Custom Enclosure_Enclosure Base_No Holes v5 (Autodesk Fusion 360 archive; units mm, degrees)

design "Custom Enclosure_Enclosure Base_No Holes" references "autodesk 3ax table head yxz"
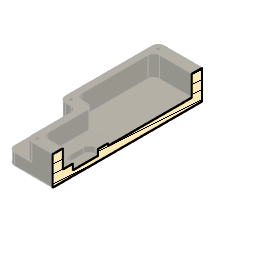
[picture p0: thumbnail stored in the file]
base_feature "Base Feature"
sketch "Sketch1" plane through (0, 0, 0) normal (0, 1, 0) x axis (1, 0, 0)
  line L1 (0, 34.798) -> (-27.94, 34.798)
  line L2 (0, 0) -> (0, 34.798)
  line L3 (-27.94, 0) -> (0, 0)
  line L4 (-27.94, 34.798) -> (-27.94, 0)
  line L5 (15, 44.5773) -> (15, 106.9773)
  line L6 (-43, 44.5773) -> (15, 44.5773)
  line L7 (-43, 106.9773) -> (-43, 44.5773)
  line L8 (15, 106.9773) -> (-43, 106.9773)
  line L9 (13.2, 46.3773) -> (11.7, 46.3773)
  line L10 (13.2, 105.1773) -> (13.2, 46.3773)
  line L11 (11.7, 105.1773) -> (13.2, 105.1773)
  line L12 (11.7, 46.3773) -> (11.7, 105.1773)
  line L13 (10, 44.5773) -> (10, 44.798)
  line L14 (-37.94, 44.798) -> (-37.94, 44.5773)
  line L15 (25, 37.5773) -> (25, 113.9773)
  line L16 (-53, 113.9773) -> (-53, 37.5773)
  line L17 (20, 118.9773) -> (-48, 118.9773)
  line L18 (-32.94, -12) -> (5, -12)
  line L19 (-37.94, 27.5773) -> (-37.94, -7)
  line L20 (-37.94, 44.798) -> (-37.94, 44.5773)
  line L21 (15, 32.5773) -> (20, 32.5773)
  line L22 (-48, 32.5773) -> (-42.94, 32.5773)
  line L23 (10, 44.5773) -> (10, 44.798)
  line L24 (10, -7) -> (10, 27.5773)
  circle C1 centre (-24.13, 1.524) radius 0.5
  circle C2 centre (-24.13, 5.09) radius 0.5
  circle C3 centre (-24.13, 7.63) radius 0.5
  circle C4 centre (-24.13, 10.17) radius 0.5
  circle C5 centre (-24.13, 12.71) radius 0.5
  circle C6 centre (-18.542, 2.54) radius 1.1
  circle C7 centre (-15.322, 17.286) radius 0.15
  circle C8 centre (-14.772, 16.736) radius 0.15
  circle C9 centre (-14.222, 17.286) radius 0.15
  circle C10 centre (-13.672, 16.736) radius 0.15
  circle C11 centre (-13.122, 17.286) radius 0.15
  circle C12 centre (-24.13, 18.288) radius 0.5
  circle C13 centre (-24.13, 20.828) radius 0.5
  circle C14 centre (-24.13, 23.368) radius 0.5
  circle C15 centre (-24.13, 25.908) radius 0.5
  circle C16 centre (-24.13, 28.448) radius 0.5
  circle C17 centre (-24.13, 30.988) radius 0.5
  circle C18 centre (-15.322, 18.386) radius 0.15
  circle C19 centre (-14.772, 17.836) radius 0.15
  circle C20 centre (-14.222, 18.386) radius 0.15
  circle C21 centre (-14.772, 18.936) radius 0.15
  circle C22 centre (-13.672, 17.836) radius 0.15
  circle C23 centre (-13.672, 18.936) radius 0.15
  circle C24 centre (-13.122, 18.386) radius 0.15
  circle C25 centre (-1.778, 1.778) radius 1.1
  circle C26 centre (-1.778, 33.02) radius 1.1
  circle C27 centre (-14, 97.9773) radius 1.44
  circle C28 centre (-14, 53.5773) radius 1.44
  arc A1 centre (-42.94, 27.5773) radius 5 clockwise from (-42.94, 32.5773) to (-37.94, 27.5773)
  arc A2 centre (-48, 37.5773) radius 5 clockwise from (-48, 32.5773) to (-53, 37.5773)
  arc A3 centre (15, 27.5773) radius 5 clockwise from (10, 27.5773) to (15, 32.5773)
  arc A4 centre (20, 37.5773) radius 5 clockwise from (25, 37.5773) to (20, 32.5773)
  arc A5 centre (-32.94, -7) radius 5 clockwise from (-32.94, -12) to (-37.94, -7)
  arc A6 centre (5, -7) radius 5 clockwise from (10, -7) to (5, -12)
  arc A7 centre (-48, 113.9773) radius 5 clockwise from (-53, 113.9773) to (-48, 118.9773)
  arc A8 centre (20, 113.9773) radius 5 clockwise from (20, 118.9773) to (25, 113.9773)
  point P44 (-37.94, 44.5773)
  point P45 (10, 44.5773)
  parallel L2 L13
  coincident L6 P44
  coincident L6 P45
  parallel L2 L23
  parallel L3 L18
  parallel L4 L19
  collinear L19 L20
  parallel L5 L15
  parallel L6 L21
  parallel L7 L16
  parallel L8 L17
  collinear L21 L22
  collinear L23 L24
  tangent L19 A1
  tangent L22 A1
  tangent L16 A2
  tangent L22 A2
  equal A1 A2
  tangent L21 A3
  tangent L24 A3
  equal A1 A3
  tangent L15 A4
  tangent L21 A4
  equal A1 A4
  tangent L18 A5
  tangent L19 A5
  equal A1 A5
  tangent L18 A6
  tangent L24 A6
  equal A1 A6
  tangent L16 A7
  tangent L17 A7
  equal A1 A7
  tangent L15 A8
  tangent L17 A8
  equal A1 A8
  dimension "d20" radius A1 = 5
  dimension "d33" distance L8 L17 = 12
  dimension "d34" distance L6 L22 = 12
  dimension "d35" distance L3 L18 = 12
extrude "Extrude1" new body sketch "Sketch1" profile of L15 L22 L16 L17 L24 L20 L18 A1 A2 A3 A4 A5 A6 A7 A8 along normal blind 18 and against normal blind 7.4
sketch "Sketch2" plane through (0, 0, 0) normal (0, 1, 0) x axis (1, 0, 0)
  line L1 (0, 34.798) -> (-27.94, 34.798)
  line L2 (0, 0) -> (0, 34.798)
  line L3 (-27.94, 0) -> (0, 0)
  line L4 (-27.94, 34.798) -> (-27.94, 0)
  line L5 (15, 44.5773) -> (15, 106.9773)
  line L6 (-43, 44.5773) -> (15, 44.5773)
  line L7 (-43, 106.9773) -> (-43, 44.5773)
  line L8 (15, 106.9773) -> (-43, 106.9773)
  line L9 (13.2, 46.3773) -> (11.7, 46.3773)
  line L10 (13.2, 105.1773) -> (13.2, 46.3773)
  line L11 (11.7, 105.1773) -> (13.2, 105.1773)
  line L12 (11.7, 46.3773) -> (11.7, 105.1773)
  line L13 (20, 46.5773) -> (20, 104.9773)
  line L14 (-48, 104.9773) -> (-48, 46.5773)
  line L15 (15, 109.9773) -> (-43, 109.9773)
  line L16 (-27.94, -3) -> (0, -3)
  line L17 (-32.94, 36.5773) -> (-32.94, 2)
  line L18 (5, 2) -> (5, 36.5773)
  line L19 (10, 41.5773) -> (15, 41.5773)
  line L20 (-43, 41.5773) -> (-37.94, 41.5773)
  circle C1 centre (-24.13, 1.524) radius 0.5
  circle C2 centre (-24.13, 5.09) radius 0.5
  circle C3 centre (-24.13, 7.63) radius 0.5
  circle C4 centre (-24.13, 10.17) radius 0.5
  circle C5 centre (-24.13, 12.71) radius 0.5
  circle C6 centre (-18.542, 2.54) radius 1.1
  circle C7 centre (-15.322, 17.286) radius 0.15
  circle C8 centre (-14.772, 16.736) radius 0.15
  circle C9 centre (-14.222, 17.286) radius 0.15
  circle C10 centre (-13.672, 16.736) radius 0.15
  circle C11 centre (-13.122, 17.286) radius 0.15
  circle C12 centre (-24.13, 18.288) radius 0.5
  circle C13 centre (-24.13, 20.828) radius 0.5
  circle C14 centre (-24.13, 23.368) radius 0.5
  circle C15 centre (-24.13, 25.908) radius 0.5
  circle C16 centre (-24.13, 28.448) radius 0.5
  circle C17 centre (-24.13, 30.988) radius 0.5
  circle C18 centre (-15.322, 18.386) radius 0.15
  circle C19 centre (-14.772, 17.836) radius 0.15
  circle C20 centre (-14.222, 18.386) radius 0.15
  circle C21 centre (-14.772, 18.936) radius 0.15
  circle C22 centre (-13.672, 17.836) radius 0.15
  circle C23 centre (-13.672, 18.936) radius 0.15
  circle C24 centre (-13.122, 18.386) radius 0.15
  circle C25 centre (-1.778, 1.778) radius 1.1
  circle C26 centre (-1.778, 33.02) radius 1.1
  circle C27 centre (-14, 97.9773) radius 1.44
  circle C28 centre (-14, 53.5773) radius 1.44
  arc A1 centre (-43, 46.5773) radius 5 clockwise from (-43, 41.5773) to (-48, 46.5773)
  arc A2 centre (-37.94, 36.5773) radius 5 clockwise from (-37.94, 41.5773) to (-32.94, 36.5773)
  arc A3 centre (-27.94, 2) radius 5 clockwise from (-27.94, -3) to (-32.94, 2)
  arc A4 centre (0, 2) radius 5 clockwise from (5, 2) to (0, -3)
  arc A5 centre (10, 36.5773) radius 5 clockwise from (5, 36.5773) to (10, 41.5773)
  arc A6 centre (15, 46.5773) radius 5 clockwise from (20, 46.5773) to (15, 41.5773)
  arc A7 centre (-43, 104.9773) radius 5 clockwise from (-48, 104.9773) to (-43, 109.9773)
  arc A8 centre (15, 104.9773) radius 5 clockwise from (15, 109.9773) to (20, 104.9773)
  parallel L3 L16
  parallel L4 L17
  parallel L2 L18
  parallel L5 L13
  parallel L6 L19
  parallel L7 L14
  parallel L8 L15
  collinear L19 L20
  tangent L14 A1
  tangent L20 A1
  tangent L20 A2
  tangent L17 A2
  tangent L16 A3
  tangent L17 A3
  equal A2 A3
  tangent L16 A4
  tangent L18 A4
  equal A2 A4
  tangent L19 A5
  tangent L18 A5
  equal A2 A5
  tangent L13 A6
  tangent L19 A6
  equal A2 A6
  tangent L14 A7
  tangent L15 A7
  equal A2 A7
  tangent L13 A8
  tangent L15 A8
  equal A2 A8
  dimension "d23" radius A1 = 5
  dimension "d24" radius A2 = 5
  dimension "d30" distance L8 L15 = 3
  dimension "d31" distance L6 L20 = 3
  dimension "d32" distance L3 L16 = 3
extrude "Extrude4" cut sketch "Sketch2" profile of L14 L13 L20 L15 L16 L18 L17 A1 A2 A3 A4 A5 A6 A7 A8 to an object
sketch "Sketch9" plane through (0, 0, 0) normal (0, 1, 0) x axis (-1, 0, 0)
  line L1 (-20, -104.9773) -> (-20, -46.5773)
  line L2 (43, -109.9773) -> (-15, -109.9773)
  line L3 (48, -46.5773) -> (48, -104.9773)
  line L4 (37.94, -41.5773) -> (43, -41.5773)
  line L5 (32.94, -2) -> (32.94, -36.5773)
  line L6 (0, 3) -> (27.94, 3)
  line L7 (-5, -36.5773) -> (-5, -2)
  line L8 (-15, -41.5773) -> (-10, -41.5773)
  line L9 (-5, -36.5773) -> (32.94, -36.5773)
  arc A1 centre (-15, -46.5773) radius 5 clockwise from (-20, -46.5773) to (-15, -41.5773)
  arc A2 centre (-15, -104.9773) radius 5 clockwise from (-15, -109.9773) to (-20, -104.9773)
  arc A3 centre (43, -104.9773) radius 5 clockwise from (48, -104.9773) to (43, -109.9773)
  arc A4 centre (43, -46.5773) radius 5 clockwise from (43, -41.5773) to (48, -46.5773)
  arc A5 centre (37.94, -36.5773) radius 5 clockwise from (37.94, -41.5773) to (32.94, -36.5773)
  arc A6 centre (27.94, -2) radius 5 clockwise from (27.94, 3) to (32.94, -2)
  arc A7 centre (0, -2) radius 5 clockwise from (-5, -2) to (0, 3)
  arc A8 centre (-10, -36.5773) radius 5 clockwise from (-5, -36.5773) to (-10, -41.5773)
  point P15 (32.94, -36.5773)
  point P26 (32.94, -36.5773)
  point P23 (-5, -36.5773)
  point P27 (-5, -36.5773)
  coincident P15 P26
  coincident P23 P27
extrude "Extrude9" add sketch "Sketch9" profile of L5 A6 L6 A7 L7 L9 along normal blind 2
sketch "Sketch3" plane through (0, 2, 0) normal (0, 1, 0) x axis (-1, 0, 0)
  line L1 (0, 5) -> (27.94, 5)
  line L2 (-5, -106.9773) -> (-5, 0)
  line L3 (53, -111.9773) -> (0, -111.9773)
  line L4 (37.94, -39.5773) -> (53, -39.5773)
  line L5 (32.94, 0) -> (32.94, -34.5773)
  line L6 (19.713, -21.28) -> (19.713, -12.23)
  line L7 (9.713, -12.23) -> (9.713, -21.28)
  line L8 (9.713, -16.755) -> (19.713, -16.755)
  line L9 (17.213, -5.755) -> (12.213, -5.755)
  line L10 (22.213, -22.755) -> (22.213, -10.755)
  line L11 (12.213, -27.755) -> (17.213, -27.755)
  line L12 (7.213, -10.755) -> (7.213, -22.755)
  line L13 (22.213, -27.755) -> (7.213, -5.755)
  line L14 (7.213, -27.755) -> (22.213, -5.755)
  line L15 (53, -39.5773) -> (53, -111.9773)
  line L16 (-20, -104.9773) -> (-20, -46.5773)
  line L17 (43, -109.9773) -> (-15, -109.9773)
  line L18 (48, -46.5773) -> (48, -104.9773)
  line L19 (37.94, -41.5773) -> (43, -41.5773)
  line L20 (-15, -41.5773) -> (-10, -41.5773)
  line L21 (-5, -36.5773) -> (32.94, -36.5773)
  line L22 (0, 3) -> (27.94, 3)
  line L23 (-5, -36.5773) -> (-5, -2)
  line L24 (32.94, -36.5773) -> (-5, -36.5773)
  line L25 (32.94, -2) -> (32.94, -36.5773)
  arc A1 centre (27.94, 0) radius 5 clockwise from (27.94, 5) to (32.94, 0)
  arc A2 centre (0, 0) radius 5 clockwise from (-5, 0) to (0, 5)
  arc A3 centre (0, -106.9773) radius 5 clockwise from (0, -111.9773) to (-5, -106.9773)
  arc A4 centre (37.94, -34.5773) radius 5 clockwise from (37.94, -39.5773) to (32.94, -34.5773)
  arc A5 centre (17.213, -22.755) radius 5 clockwise from (22.213, -22.755) to (17.213, -27.755)
  arc A6 centre (17.213, -10.755) radius 5 clockwise from (17.213, -5.755) to (22.213, -10.755)
  arc A7 centre (12.213, -10.755) radius 5 clockwise from (7.213, -10.755) to (12.213, -5.755)
  arc A8 centre (12.213, -22.755) radius 5 clockwise from (12.213, -27.755) to (7.213, -22.755)
  arc A9 centre (-15, -46.5773) radius 5 clockwise from (-20, -46.5773) to (-15, -41.5773)
  arc A10 centre (-15, -104.9773) radius 5 clockwise from (-15, -109.9773) to (-20, -104.9773)
  arc A11 centre (43, -104.9773) radius 5 clockwise from (48, -104.9773) to (43, -109.9773)
  arc A12 centre (43, -46.5773) radius 5 clockwise from (43, -41.5773) to (48, -46.5773)
  arc A13 centre (37.94, -36.5773) radius 5 clockwise from (37.94, -41.5773) to (32.94, -36.5773)
  arc A14 centre (-10, -36.5773) radius 5 clockwise from (-5, -36.5773) to (-10, -41.5773)
  arc A15 centre (27.94, -2) radius 5 clockwise from (27.94, 3) to (32.94, -2)
  arc A16 centre (0, -2) radius 5 clockwise from (-5, -2) to (0, 3)
  point P20 (19.713, -16.755)
  point P21 (9.713, -16.755)
  point P26 (14.713, -16.755)
  point P24 (22.213, -27.755)
  point P23 (22.213, -5.755)
  point P22 (7.213, -5.755)
  point P25 (7.213, -27.755)
  midpoint L6 P20
  midpoint L7 P21
  horizontal L9
  perpendicular L9 L10
  parallel L9 L11
  parallel L10 L12
  coincident L13 P26
  coincident L14 P26
  midpoint L8 P26
  coincident P24 L11
  coincident P24 L10
  tangent L11 A5
  tangent L10 A5
  coincident P23 L10
  coincident P23 L9
  tangent L10 A6
  tangent L9 A6
  equal A5 A6
  coincident P22 L12
  coincident P22 L9
  tangent L12 A7
  tangent L9 A7
  equal A5 A7
  coincident P25 L11
  coincident P25 L12
  tangent L11 A8
  tangent L12 A8
  equal A5 A8
  dimension "d13" distance P22 P23 = 15
  dimension "d14" distance P22 P25 = 22
  dimension "d17" radius A5 = 5
extrude "Extrude3" cut sketch "Sketch3" profile of L9 L10 L11 L12 A5 A6 A7 A8 against normal blind 5
sketch "Sketch4" plane through (0, -7.4, 0) normal (0, -1, 0) x axis (1, 0, 0)
  line L1 (15, -32.5773) -> (20, -32.5773)
  line L2 (10, 7) -> (10, -27.5773)
  line L3 (-32.94, 12) -> (5, 12)
  line L4 (-37.94, -27.5773) -> (-37.94, 7)
  line L5 (-48, -32.5773) -> (-42.94, -32.5773)
  line L6 (-53, -113.9773) -> (-53, -37.5773)
  line L7 (20, -118.9773) -> (-48, -118.9773)
  line L8 (25, -37.5773) -> (25, -113.9773)
  line L9 (-48, 12) -> (-32.94, 12)
  line L10 (-53, -37.5773) -> (-53, 7)
  line L11 (-32.94, -37.5773) -> (-53, -37.5773)
  line L12 (-32.94, 12) -> (-32.94, -37.5773)
  line L13 (20, 12) -> (5, 12)
  line L14 (25, -37.5773) -> (25, 7)
  line L15 (5, -37.5773) -> (25, -37.5773)
  line L16 (5, 12) -> (5, -37.5773)
  line L17 (-14, -118.9773) -> (-13.97, 12)
  arc A1 centre (20, -37.5773) radius 5 clockwise from (20, -32.5773) to (25, -37.5773)
  arc A2 centre (15, -27.5773) radius 5 clockwise from (15, -32.5773) to (10, -27.5773)
  arc A3 centre (5, 7) radius 5 clockwise from (5, 12) to (10, 7)
  arc A4 centre (-32.94, 7) radius 5 clockwise from (-37.94, 7) to (-32.94, 12)
  arc A5 centre (-42.94, -27.5773) radius 5 clockwise from (-37.94, -27.5773) to (-42.94, -32.5773)
  arc A6 centre (-48, -37.5773) radius 5 clockwise from (-53, -37.5773) to (-48, -32.5773)
  arc A7 centre (-48, -113.9773) radius 5 clockwise from (-48, -118.9773) to (-53, -113.9773)
  arc A8 centre (20, -113.9773) radius 5 clockwise from (25, -113.9773) to (20, -118.9773)
  arc A9 centre (-48, 7) radius 5 clockwise from (-53, 7) to (-48, 12)
  arc A10 centre (20, 7) radius 5 clockwise from (20, 12) to (25, 7)
  circle C1 centre (-45, -24) radius 3.05
  circle C2 centre (17.0435, -24.0142) radius 3.05
  point P18 (-53, -37.5773)
  point P27 (-53, -37.5773)
  point P11 (-32.94, 12)
  point P26 (-32.94, 12)
  point P2 (25, -37.5773)
  point P30 (25, -37.5773)
  point P9 (5, 12)
  point P29 (5, 12)
  point P39 (-13.97, 12)
  point P40 (-14, -118.9773)
  point P38 (-45, -24)
  horizontal L9
  vertical L10
  horizontal L11
  vertical L12
  coincident P18 P27
  coincident P11 P26
  horizontal L13
  vertical L14
  horizontal L15
  vertical L16
  coincident P2 P30
  coincident P9 P29
  tangent L9 A9
  tangent L10 A9
  tangent L13 A10
  tangent L14 A10
  equal A9 A10
  midpoint L3 P39
  midpoint L7 P40
  symmetric C1 L17 C2
  dimension "d27" radius A9 = 5
  dimension "d67" diameter C1 = 6.1
  dimension "d68" distance L10 P38 = 8
  dimension "d69" distance L9 P38 = 36
extrude "Extrude5" add sketch "Sketch4" profile of A1 L1 A2 L2 A3 A4 L4 A5 L5 A6 L9 L10 L13 L14 A9 A10 C1 C2 against normal blind 10
sketch "Sketch6" plane through (0, 18, 0) normal (0, 1, 0) x axis (-1, 0, 0)
  line L1 (43, -41.5773) -> (37.94, -41.5773)
  line L2 (48, -104.9773) -> (48, -46.5773)
  line L3 (-15, -109.9773) -> (43, -109.9773)
  line L4 (-20, -46.5773) -> (-20, -104.9773)
  line L5 (-10, -41.5773) -> (-15, -41.5773)
  line L6 (-5, -2) -> (-5, -36.5773)
  line L7 (27.94, 3) -> (0, 3)
  line L8 (32.94, -36.5773) -> (32.94, -2)
  line L9 (-25, -113.9773) -> (-25, -37.5773)
  line L10 (48, -118.9773) -> (-20, -118.9773)
  line L11 (53, -37.5773) -> (53, -113.9773)
  line L12 (42.94, -32.5773) -> (48, -32.5773)
  line L13 (37.94, 7) -> (37.94, -27.5773)
  line L14 (-5, 12) -> (32.94, 12)
  line L15 (-10, -27.5773) -> (-10, 7)
  line L16 (-20, -32.5773) -> (-15, -32.5773)
  line L17 (13.97, 12) -> (14, -118.9773)
  arc A1 centre (43, -46.5773) radius 5 clockwise from (43, -41.5773) to (48, -46.5773)
  arc A2 centre (43, -104.9773) radius 5 clockwise from (48, -104.9773) to (43, -109.9773)
  arc A3 centre (-15, -104.9773) radius 5 clockwise from (-15, -109.9773) to (-20, -104.9773)
  arc A4 centre (-15, -46.5773) radius 5 clockwise from (-20, -46.5773) to (-15, -41.5773)
  arc A5 centre (-10, -36.5773) radius 5 clockwise from (-5, -36.5773) to (-10, -41.5773)
  arc A6 centre (0, -2) radius 5 clockwise from (-5, -2) to (0, 3)
  arc A7 centre (27.94, -2) radius 5 clockwise from (27.94, 3) to (32.94, -2)
  arc A8 centre (37.94, -36.5773) radius 5 clockwise from (37.94, -41.5773) to (32.94, -36.5773)
  arc A9 centre (-20, -37.5773) radius 5 clockwise from (-25, -37.5773) to (-20, -32.5773)
  arc A10 centre (-20, -113.9773) radius 5 clockwise from (-20, -118.9773) to (-25, -113.9773)
  arc A11 centre (48, -113.9773) radius 5 clockwise from (53, -113.9773) to (48, -118.9773)
  arc A12 centre (48, -37.5773) radius 5 clockwise from (48, -32.5773) to (53, -37.5773)
  arc A13 centre (42.94, -27.5773) radius 5 clockwise from (42.94, -32.5773) to (37.94, -27.5773)
  arc A14 centre (32.94, 7) radius 5 clockwise from (32.94, 12) to (37.94, 7)
  arc A15 centre (-5, 7) radius 5 clockwise from (-10, 7) to (-5, 12)
  arc A16 centre (-15, -27.5773) radius 5 clockwise from (-10, -27.5773) to (-15, -32.5773)
  circle C1 centre (48, -113.9773) radius 1.45
  circle C2 centre (48, -37.5773) radius 1.45
  circle C3 centre (32.94, 7) radius 1.45
  circle C4 centre (-20.0023, -113.9929) radius 1.45
  circle C5 centre (-20.0373, -37.5929) radius 1.45
  circle C6 centre (-4.9977, 6.9913) radius 1.45
  point P53 (14, -118.9773)
  point P54 (13.97, 12)
  concentric A11 C1
  concentric A12 C2
  concentric A14 C3
  equal C2 C3
  equal C1 C2
  midpoint L10 P53
  midpoint L14 P54
  symmetric C1 L17 C4
  symmetric C2 L17 C5
  symmetric C3 L17 C6
  dimension "d40" diameter C1 = 2.9
extrude "Extrude6" cut sketch "Sketch6" profile of C1 C2 C3 C4 C5 C6 against normal blind 10
sketch "Sketch7" plane through (0, 2, 0) normal (0, 1, 0) x axis (-1, 0, 0)
  line L1 (7.213, -10.755) -> (7.213, -22.755)
  line L2 (17.213, -5.755) -> (12.213, -5.755)
  line L3 (22.213, -22.755) -> (22.213, -10.755)
  line L4 (12.213, -27.755) -> (17.213, -27.755)
  line L5 (-20, -104.9773) -> (-20, -46.5773)
  line L6 (43, -109.9773) -> (-15, -109.9773)
  line L7 (48, -46.5773) -> (48, -104.9773)
  line L8 (37.94, -41.5773) -> (43, -41.5773)
  line L9 (32.94, -2) -> (32.94, -36.5773)
  line L10 (0, 3) -> (27.94, 3)
  line L11 (-5, -36.5773) -> (-5, -2)
  line L12 (-15, -41.5773) -> (-10, -41.5773)
  line L13 (7.213, -10.755) -> (7.213, -22.755)
  line L14 (17.213, -5.755) -> (12.213, -5.755)
  line L15 (22.213, -22.755) -> (22.213, -10.755)
  line L16 (12.213, -27.755) -> (17.213, -27.755)
  line L17 (0, 3) -> (27.94, 3)
  line L18 (-5, -36.5773) -> (-5, -2)
  line L19 (32.94, -36.5773) -> (-5, -36.5773)
  line L20 (32.94, -2) -> (32.94, -36.5773)
  arc A1 centre (12.213, -10.755) radius 5 clockwise from (7.213, -10.755) to (12.213, -5.755)
  arc A2 centre (17.213, -10.755) radius 5 clockwise from (17.213, -5.755) to (22.213, -10.755)
  arc A3 centre (17.213, -22.755) radius 5 clockwise from (22.213, -22.755) to (17.213, -27.755)
  arc A4 centre (12.213, -22.755) radius 5 clockwise from (12.213, -27.755) to (7.213, -22.755)
  arc A5 centre (-15, -46.5773) radius 5 clockwise from (-20, -46.5773) to (-15, -41.5773)
  arc A6 centre (-15, -104.9773) radius 5 clockwise from (-15, -109.9773) to (-20, -104.9773)
  arc A7 centre (43, -104.9773) radius 5 clockwise from (48, -104.9773) to (43, -109.9773)
  arc A8 centre (43, -46.5773) radius 5 clockwise from (43, -41.5773) to (48, -46.5773)
  arc A9 centre (37.94, -36.5773) radius 5 clockwise from (37.94, -41.5773) to (32.94, -36.5773)
  arc A10 centre (27.94, -2) radius 5 clockwise from (27.94, 3) to (32.94, -2)
  arc A11 centre (0, -2) radius 5 clockwise from (-5, -2) to (0, 3)
  arc A12 centre (-10, -36.5773) radius 5 clockwise from (-5, -36.5773) to (-10, -41.5773)
  circle C1 centre (1.778, -33.02) radius 1.1
  circle C2 centre (18.542, -2.54) radius 1.1
  circle C3 centre (1.778, -1.778) radius 1.1
  circle C4 centre (1.778, -33.02) radius 0.95
  circle C5 centre (18.542, -2.54) radius 0.95
  circle C6 centre (1.778, -1.778) radius 0.95
  arc A13 centre (12.213, -10.755) radius 5 clockwise from (7.213, -10.755) to (12.213, -5.755)
  arc A14 centre (17.213, -10.755) radius 5 clockwise from (17.213, -5.755) to (22.213, -10.755)
  arc A15 centre (17.213, -22.755) radius 5 clockwise from (22.213, -22.755) to (17.213, -27.755)
  arc A16 centre (12.213, -22.755) radius 5 clockwise from (12.213, -27.755) to (7.213, -22.755)
  arc A17 centre (27.94, -2) radius 5 clockwise from (27.94, 3) to (32.94, -2)
  arc A18 centre (0, -2) radius 5 clockwise from (-5, -2) to (0, 3)
  concentric C1 C4
  concentric C2 C5
  concentric C3 C6
  equal C4 C6
  equal C5 C6
  dimension "d91" diameter C5 = 1.9
extrude "Extrude7" cut sketch "Sketch7" profile of C4 C5 C6 against normal blind 4
sketch "Sketch8" plane through (0, 0, 3) normal (0, 0, -1) x axis (-1, 0, 0)
  line L1 (0, 18) -> (27.94, 18)
  line L2 (0, 0) -> (0, 18)
  line L3 (27.94, 0) -> (0, 0)
  line L4 (27.94, 18) -> (27.94, 0)
  line L5 (10.14, 2.4) -> (7.64, 2.4)
  line L6 (8.89, 4.9) -> (8.89, 2.4)
  circle C1 centre (8.89, 4.9) radius 2.5
  point P9 (8.89, 2.4)
  point P8 (8.89, 4.9)
  point P10 (8.89, 4.9)
  midpoint L5 P9
  perpendicular L5 L6
  coincident P8 P10
  tangent L5 C1
  dimension "d92" diameter C1 = 5
extrude "Extrude8" cut sketch "Sketch8" profile of C1 to an object
fillet "Fillet1" radius 5 5

design "autodesk 3ax table head yxz"
named bodies: "base", "y_axis_head", "x_axis_head", "z_axis_head"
